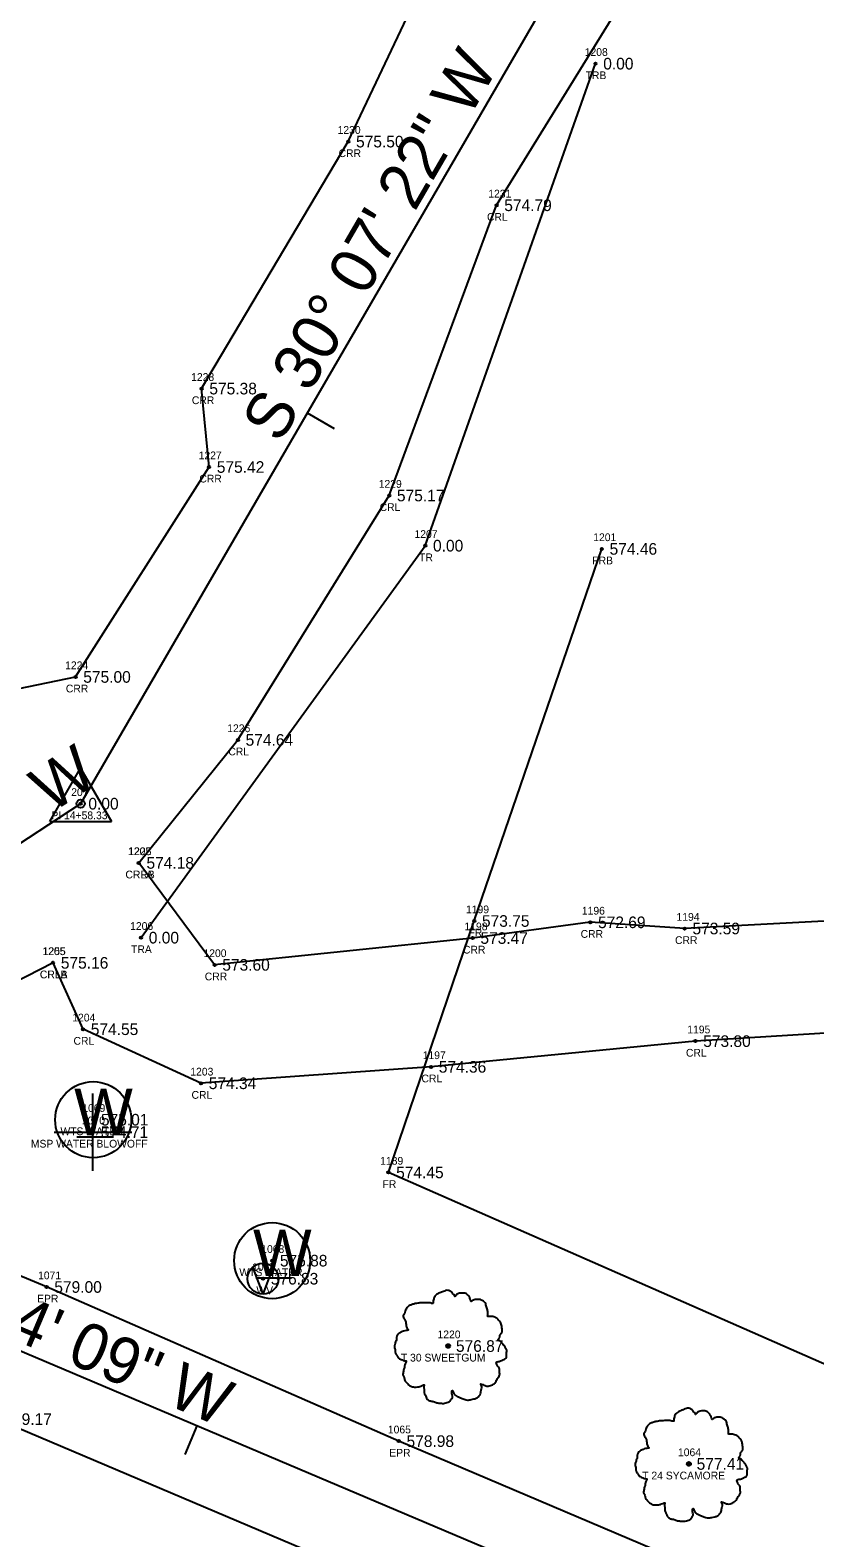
# Model space of a CAD drawing. Extents: x 1664393 to 1667175, y 987029 to 988607.
# Drawn here: x 1665562.7 to 1665664.1, y 987718.5 to 987913.2 of the extents above; entities that cross this region are included whole.
import ezdxf

# ---------------------------------------------------------------- set-up
doc = ezdxf.new("R2010")
doc.units = 0
for name, color, linetype in [('RD_EX_Fence_Other', 7, 'Continuous'), ('RD_EX_Fence_Other_txCode', 7, 'Continuous'), ('RD_EX_H2O', 7, 'Continuous'), ('RD_EX_H2O_txCode', 7, 'Continuous'), ('RD_EX_Misc', 7, 'Continuous'), ('RD_EX_Misc_txCode', 7, 'Continuous'), ('RD_EX_Road', 7, 'Continuous'), ('RD_EX_Road_txCode', 7, 'Continuous'), ('RD_EX_TX_Fence_Other_ELEV', 7, 'Continuous'), ('RD_EX_TX_H2O_ELEV', 7, 'Continuous'), ('RD_EX_TX_Misc_ELEV', 7, 'Continuous'), ('RD_EX_TX_Road_ELEV', 7, 'Continuous'), ('RD_EX_TX_UT_ELEV', 7, 'Continuous'), ('RD_EX_TX_VEG_ELEV', 7, 'Continuous'), ('RD_EX_UT', 7, 'Continuous'), ('RD_EX_UT_txCode', 7, 'Continuous'), ('RD_EX_VEG', 7, 'Continuous'), ('RD_EX_VEG_txCode', 7, 'Continuous'), ('RD_HC_Cl', 7, 'Continuous'), ('RD_HC_Data', 7, 'Continuous'), ('RD_HC_Data_Tic', 7, 'Continuous'), ('RD_HC_Survey_ELEV', 7, 'Continuous'), ('RD_HC_txCode', 7, 'Continuous'), ('RD_SMD_Locator', 7, 'Continuous')]:
    doc.layers.add(name, color=color, linetype=linetype)

msp = doc.modelspace()

# ---------------------------------------------------------------- linework, layer by layer
at = {"layer": 'RD_EX_Fence_Other'}
msp.add_lwpolyline([(1666177.67, 987530.31), (1666129.01, 987549.76), (1665988.61, 987609.56), (1665898.39, 987650), (1665744.33, 987706.22), (1665608.99, 987765.72), (1665620.07, 987798.18), (1665636.55, 987846.22)], dxfattribs=at)
at = {"layer": 'RD_EX_H2O'}
for points in [[(1665526.5, 987797.57), (1665535.59, 987808.2), (1665547.98, 987825.42), (1665568.59, 987829.69), (1665585.83, 987856.79), (1665584.87, 987866.91), (1665603.81, 987898.8), (1665618.99, 987930.85), (1665645.33, 987961.5), (1665639.67, 987994.37), (1665644.94, 988008.07), (1665639.5, 988048.94), (1665653.76, 988079.25), (1665684.31, 988124.82), (1665706.22, 988174.88), (1665711.8, 988227.54)], [(1665576.75, 987805.68), (1665589.55, 987821.56), (1665609.09, 987853.11), (1665622.95, 987890.58), (1665641.35, 987920.45), (1665654.29, 987935.19), (1665658.75, 987952.97), (1665657.67, 987971.74), (1665650.8, 987993.69), (1665662.98, 988008.61), (1665660.68, 988035.04), (1665652.89, 988045.21), (1665674.32, 988062.08), (1665698.86, 988119.64), (1665728.36, 988166.73), (1665725.83, 988226.06)], [(1665735.12, 987792.87), (1665681.63, 987799.03), (1665647.25, 987797.21), (1665635.06, 987798.01), (1665619.87, 987795.98), (1665586.54, 987792.52), (1665576.75, 987805.68)], [(1665565.69, 987792.78), (1665555.48, 987787.59), (1665542.58, 987772.17), (1665532.86, 987767.81), (1665532.86, 987767.81), (1665523.69, 987745.83), (1665522.12, 987740.87), (1665518.2, 987735.79), (1665482.82, 987708), (1665483.87, 987700.87), (1665513.49, 987706.09), (1665528.04, 987685.52), (1665561.97, 987665.98), (1665593.48, 987679.22), (1665619.37, 987685.12), (1665642.78, 987680.31), (1665663.97, 987651.85), (1665686.03, 987634.26), (1665705.62, 987627.98), (1665724.83, 987594.97)], [(1665733.23, 987780.02), (1665683.57, 987784.8), (1665648.64, 987782.67), (1665614.49, 987779.35), (1665584.79, 987777.23), (1665569.56, 987784.21), (1665565.69, 987792.78)]]:
    msp.add_lwpolyline(points, dxfattribs=at)
at = {"layer": 'RD_EX_Misc'}
for p, q in [((1665570.84, 987765.93), (1665570.84, 987775.93)), ((1665565.84, 987770.93), (1665575.84, 987770.93))]:
    msp.add_line(p, q, dxfattribs=at)
at = {"layer": 'RD_EX_Road'}
for points in [[(1666163.18, 987497.62), (1666116.6, 987517.39), (1666070.7, 987536.94), (1666024.42, 987556.43), (1665979.02, 987575.67), (1665932.35, 987595.55), (1665886.93, 987614.54), (1665839.87, 987634.25), (1665794.5, 987653.27), (1665748.81, 987672.51), (1665702.36, 987691.87), (1665656.42, 987711.45), (1665610.33, 987731.03), (1665564.85, 987750.93), (1665531.47, 987764.82)], [(1666156.67, 987480.61), (1666109.28, 987500.74), (1666063.55, 987520.04), (1666017.04, 987539.82), (1665971.11, 987559.14), (1665924.88, 987578.79), (1665879.5, 987597.89), (1665833.22, 987617.38), (1665786.91, 987636.81), (1665741.44, 987656.13), (1665695.81, 987675.2), (1665649.26, 987694.85), (1665603.56, 987714.71), (1665558.4, 987733.87), (1665524.71, 987748.93)]]:
    msp.add_lwpolyline(points, dxfattribs=at)
at = {"layer": 'RD_EX_UT'}
for p, q in [((1665568.75, 987770.32), (1665573.38, 987770.32)), ((1665592.8, 987750.01), (1665591.49, 987753.49)), ((1665592.8, 987750.01), (1665594.12, 987753.45)), ((1665591.85, 987752.12), (1665596.48, 987752.12))]:
    msp.add_line(p, q, dxfattribs=at)
for centre, radius in [((1665570.87, 987772.53), 4.91), ((1665593.98, 987754.33), 4.91), ((1665592.8, 987752), 2)]:
    msp.add_circle(centre, radius, dxfattribs=at)
at = {"layer": 'RD_EX_VEG'}
msp.add_lwpolyline([(1665577.05, 987796.03), (1665613.75, 987846.63), (1665635.73, 987908.86)], dxfattribs=at)
for centre, radius in [((1665616.71, 987743.31), 0.25), ((1665616.7, 987743.29), 0.0001), ((1665647.79, 987728.09), 0.25), ((1665647.78, 987728.08), 0.0001)]:
    msp.add_circle(centre, radius, dxfattribs=at)
for points in [[(1665616.85, 987750.48), (1665616.55, 987750.5), (1665616.22, 987750.4), (1665615.97, 987750.3), (1665615.75, 987750.23), (1665615.52, 987750.13), (1665615.22, 987749.95), (1665615, 987749.75), (1665614.87, 987749.5), (1665614.82, 987749.28), (1665614.77, 987749), (1665614.77, 987748.83), (1665614.65, 987748.8), (1665614.5, 987748.83), (1665614.25, 987748.9), (1665614, 987748.9), (1665613.75, 987748.9), (1665613.4, 987748.88), (1665613.05, 987748.88), (1665612.77, 987748.83), (1665612.45, 987748.78), (1665612.07, 987748.66), (1665611.72, 987748.53), (1665611.42, 987748.28), (1665611.17, 987747.81), (1665611.05, 987747.46), (1665610.9, 987747.21), (1665611.05, 987746.76), (1665611.22, 987746.41), (1665611.25, 987746.21), (1665611.32, 987745.78), (1665611.42, 987745.56), (1665611.55, 987745.36), (1665611.47, 987745.33), (1665611.1, 987745.28), (1665610.8, 987745.18), (1665610.37, 987744.96), (1665610.15, 987744.73), (1665610.05, 987744.41), (1665610.02, 987744.06), (1665609.92, 987743.86), (1665609.85, 987743.58), (1665609.82, 987743.51), (1665609.77, 987743.18), (1665609.87, 987742.73), (1665609.9, 987742.38), (1665610.02, 987742.16), (1665610.17, 987741.98), (1665610.35, 987741.73), (1665610.75, 987741.51), (1665611.07, 987741.41), (1665611.27, 987741.38), (1665611.1, 987740.88), (1665611.05, 987740.53), (1665610.92, 987740.13), (1665610.92, 987740.06), (1665610.87, 987739.58), (1665611.02, 987739.26), (1665611.1, 987738.88), (1665611.27, 987738.66), (1665611.55, 987738.36), (1665611.87, 987738.13), (1665612.37, 987738.01), (1665612.77, 987738.03), (1665613.35, 987738.21), (1665613.6, 987738.28), (1665613.57, 987738.11), (1665613.6, 987737.73), (1665613.6, 987737.31), (1665613.75, 987736.99), (1665613.85, 987736.71), (1665614, 987736.46), (1665614.32, 987736.24), (1665614.72, 987736.16), (1665615.15, 987736.01), (1665615.6, 987735.94), (1665616.1, 987735.91), (1665616.7, 987736.06), (1665616.97, 987736.19), (1665617.07, 987736.36), (1665617.27, 987736.74), (1665617.22, 987736.96), (1665617.25, 987737.56), (1665617.35, 987737.38), (1665617.52, 987737.04), (1665618.02, 987736.74), (1665618.42, 987736.56), (1665618.89, 987736.41), (1665619.19, 987736.34), (1665619.67, 987736.41), (1665620.04, 987736.49), (1665620.42, 987736.61), (1665620.72, 987736.89), (1665620.89, 987737.16), (1665620.94, 987737.43), (1665621.02, 987737.81), (1665621.07, 987737.98)], [(1665621.07, 987737.98), (1665620.99, 987738.16), (1665620.94, 987738.41), (1665621.02, 987738.38), (1665621.19, 987738.33), (1665621.47, 987738.21), (1665621.69, 987738.13), (1665622.02, 987738.16), (1665622.29, 987738.26), (1665622.74, 987738.53), (1665623.02, 987739.01), (1665623.29, 987739.41), (1665623.37, 987739.73), (1665623.32, 987739.96), (1665623.29, 987740.46), (1665623.09, 987740.71), (1665623.04, 987740.83), (1665622.94, 987741.23), (1665623.02, 987741.28), (1665623.29, 987741.33), (1665623.67, 987741.46), (1665623.94, 987741.58), (1665624.17, 987741.76), (1665624.24, 987741.98), (1665624.22, 987742.38), (1665624.27, 987742.78), (1665624.19, 987742.93), (1665624.09, 987743.08), (1665624.02, 987743.28), (1665623.87, 987743.43), (1665623.77, 987743.58), (1665623.67, 987743.68), (1665623.54, 987743.83), (1665623.37, 987743.96), (1665623.22, 987744.01), (1665623.17, 987744.16), (1665623.32, 987744.36), (1665623.37, 987744.46), (1665623.39, 987744.68), (1665623.62, 987745.03), (1665623.67, 987745.43), (1665623.62, 987745.86), (1665623.57, 987746.13), (1665623.42, 987746.41), (1665623.22, 987746.66), (1665623.09, 987746.83), (1665622.92, 987746.96), (1665622.59, 987747.08), (1665622.34, 987747.13), (1665621.99, 987747.13), (1665621.79, 987747.18), (1665621.82, 987747.23), (1665621.82, 987747.38), (1665621.82, 987747.66), (1665621.74, 987748.11), (1665621.59, 987748.61), (1665621.59, 987748.63), (1665621.49, 987748.88), (1665621.27, 987749.08), (1665621.09, 987749.18), (1665620.89, 987749.3), (1665620.64, 987749.33), (1665620.34, 987749.33), (1665620.07, 987749.28), (1665619.87, 987749.18), (1665619.69, 987749.05), (1665619.62, 987749.2), (1665619.52, 987749.5), (1665619.47, 987749.65), (1665619.32, 987749.83), (1665619.09, 987750.03), (1665618.64, 987750.15), (1665618.02, 987750.08), (1665617.72, 987749.88), (1665617.57, 987749.7), (1665617.52, 987749.83), (1665617.32, 987750.03), (1665617.22, 987750.2), (1665617.05, 987750.33), (1665616.9, 987750.43), (1665616.8, 987750.48)], [(1665647.93, 987735.26), (1665647.63, 987735.29), (1665647.3, 987735.19), (1665647.05, 987735.09), (1665646.83, 987735.01), (1665646.6, 987734.91), (1665646.3, 987734.74), (1665646.08, 987734.54), (1665645.95, 987734.29), (1665645.9, 987734.06), (1665645.85, 987733.79), (1665645.85, 987733.61), (1665645.73, 987733.59), (1665645.58, 987733.61), (1665645.33, 987733.69), (1665645.08, 987733.69), (1665644.83, 987733.69), (1665644.48, 987733.66), (1665644.13, 987733.66), (1665643.85, 987733.61), (1665643.53, 987733.56), (1665643.15, 987733.44), (1665642.8, 987733.31), (1665642.5, 987733.06), (1665642.25, 987732.59), (1665642.13, 987732.24), (1665641.98, 987731.99), (1665642.13, 987731.54), (1665642.3, 987731.19), (1665642.33, 987730.99), (1665642.4, 987730.56), (1665642.5, 987730.34), (1665642.63, 987730.14), (1665642.55, 987730.11), (1665642.18, 987730.06), (1665641.88, 987729.96), (1665641.45, 987729.74), (1665641.23, 987729.51), (1665641.13, 987729.19), (1665641.1, 987728.84), (1665641, 987728.64), (1665640.93, 987728.37), (1665640.9, 987728.29), (1665640.85, 987727.97), (1665640.95, 987727.52), (1665640.98, 987727.17), (1665641.1, 987726.94), (1665641.25, 987726.77), (1665641.43, 987726.52), (1665641.83, 987726.29), (1665642.15, 987726.19), (1665642.35, 987726.17), (1665642.18, 987725.67), (1665642.13, 987725.32), (1665642, 987724.92), (1665642, 987724.84), (1665641.95, 987724.37), (1665642.1, 987724.04), (1665642.18, 987723.67), (1665642.35, 987723.44), (1665642.63, 987723.14), (1665642.95, 987722.92), (1665643.45, 987722.79), (1665643.85, 987722.82), (1665644.43, 987722.99), (1665644.68, 987723.07), (1665644.65, 987722.89), (1665644.68, 987722.52), (1665644.68, 987722.09), (1665644.83, 987721.77), (1665644.93, 987721.49), (1665645.08, 987721.24), (1665645.4, 987721.02), (1665645.8, 987720.94), (1665646.23, 987720.79), (1665646.68, 987720.72), (1665647.18, 987720.69), (1665647.78, 987720.84), (1665648.05, 987720.97), (1665648.15, 987721.14), (1665648.35, 987721.52), (1665648.3, 987721.74), (1665648.33, 987722.34), (1665648.43, 987722.17), (1665648.6, 987721.82), (1665649.1, 987721.52), (1665649.5, 987721.34), (1665649.98, 987721.19), (1665650.28, 987721.12), (1665650.75, 987721.19), (1665651.12, 987721.27), (1665651.5, 987721.39), (1665651.8, 987721.67), (1665651.97, 987721.94), (1665652.02, 987722.22), (1665652.1, 987722.59), (1665652.15, 987722.77)], [(1665652.15, 987722.77), (1665652.07, 987722.94), (1665652.02, 987723.19), (1665652.1, 987723.17), (1665652.27, 987723.12), (1665652.55, 987722.99), (1665652.77, 987722.92), (1665653.1, 987722.94), (1665653.37, 987723.04), (1665653.82, 987723.32), (1665654.1, 987723.79), (1665654.37, 987724.19), (1665654.45, 987724.52), (1665654.4, 987724.74), (1665654.37, 987725.24), (1665654.17, 987725.49), (1665654.12, 987725.62), (1665654.02, 987726.02), (1665654.1, 987726.07), (1665654.37, 987726.12), (1665654.75, 987726.24), (1665655.02, 987726.37), (1665655.25, 987726.54), (1665655.32, 987726.77), (1665655.3, 987727.17), (1665655.35, 987727.57), (1665655.27, 987727.72), (1665655.17, 987727.87), (1665655.1, 987728.07), (1665654.95, 987728.22), (1665654.85, 987728.37), (1665654.75, 987728.46), (1665654.62, 987728.61), (1665654.45, 987728.74), (1665654.3, 987728.79), (1665654.25, 987728.94), (1665654.4, 987729.14), (1665654.45, 987729.24), (1665654.47, 987729.46), (1665654.7, 987729.81), (1665654.75, 987730.21), (1665654.7, 987730.64), (1665654.65, 987730.91), (1665654.5, 987731.19), (1665654.3, 987731.44), (1665654.17, 987731.61), (1665654, 987731.74), (1665653.67, 987731.86), (1665653.42, 987731.91), (1665653.07, 987731.91), (1665652.87, 987731.96), (1665652.9, 987732.01), (1665652.9, 987732.16), (1665652.9, 987732.44), (1665652.82, 987732.89), (1665652.67, 987733.39), (1665652.67, 987733.41), (1665652.57, 987733.66), (1665652.35, 987733.86), (1665652.17, 987733.96), (1665651.97, 987734.09), (1665651.72, 987734.11), (1665651.42, 987734.11), (1665651.15, 987734.06), (1665650.95, 987733.96), (1665650.78, 987733.84), (1665650.7, 987733.99), (1665650.6, 987734.29), (1665650.55, 987734.44), (1665650.4, 987734.61), (1665650.18, 987734.81), (1665649.73, 987734.94), (1665649.1, 987734.86), (1665648.8, 987734.66), (1665648.65, 987734.49), (1665648.6, 987734.61), (1665648.4, 987734.81), (1665648.3, 987734.99), (1665648.13, 987735.11), (1665647.98, 987735.21), (1665647.88, 987735.26)]]:
    msp.add_spline(points, degree=3, dxfattribs=at)
at = {"layer": 'RD_HC_Cl'}
for p, q in [((1666160.05, 987489.41), (1664963.07, 987995.8)), ((1665651.17, 987954.51), (1665569.25, 987813.32)), ((1665569.25, 987813.32), (1665529.15, 987787.05))]:
    msp.add_line(p, q, dxfattribs=at)
at = {"layer": 'RD_HC_Data'}
for p, q in [((1665565.28, 987811.02), (1665569.25, 987817.9)), ((1665569.25, 987817.9), (1665573.22, 987811.02)), ((1665565.28, 987811.02), (1665573.22, 987811.02))]:
    msp.add_line(p, q, dxfattribs=at)
msp.add_circle((1665569.25, 987813.32), 0.529, dxfattribs=at)
at = {"layer": 'RD_HC_Data_Tic'}
for p, q in [((1665598.52, 987863.77), (1665601.98, 987861.77)), ((1665584.25, 987733.01), (1665582.69, 987729.32))]:
    msp.add_line(p, q, dxfattribs=at)
at = {"layer": 'RD_SMD_Locator'}
for centre in [(1665635.73, 987908.86), (1665603.81, 987898.8), (1665622.95, 987890.58), (1665584.87, 987866.91), (1665585.83, 987856.79), (1665609.09, 987853.11), (1665613.75, 987846.63), (1665636.55, 987846.22), (1665568.59, 987829.69), (1665589.55, 987821.56), (1665569.25, 987813.32), (1665576.75, 987805.68), (1665576.75, 987805.68), (1665620.07, 987798.18), (1665635.06, 987798.01), (1665647.25, 987797.21), (1665577.05, 987796.03), (1665619.87, 987795.98), (1665565.69, 987792.78), (1665565.69, 987792.78), (1665586.54, 987792.52), (1665569.56, 987784.21), (1665648.64, 987782.67), (1665614.49, 987779.35), (1665584.79, 987777.23), (1665570.87, 987772.53), (1665570.84, 987770.93), (1665608.99, 987765.72), (1665593.98, 987754.33), (1665564.85, 987750.93), (1665592.8, 987752), (1665616.71, 987743.31), (1665610.33, 987731.03), (1665647.79, 987728.09)]:
    msp.add_circle(centre, 0.15, dxfattribs=at)

# ---------------------------------------------------------------- texts
at = {"layer": 'RD_EX_Fence_Other_txCode'}
for s, p in [('1201', (1665635.44, 987847.22)), ('FRB', (1665635.32, 987844.22)), ('1199', (1665619.01, 987799.18)), ('FR', (1665619.32, 987796.18)), ('1189', (1665607.93, 987766.72)), ('FR', (1665608.23, 987763.72))]:
    msp.add_text(s, height=1, dxfattribs=at).set_placement(p)
at = {"layer": 'RD_EX_H2O_txCode'}
for s, p in [('1230', (1665602.43, 987899.8)), ('CRR', (1665602.56, 987896.8)), ('1231', (1665621.89, 987891.58)), ('CRL', (1665621.72, 987888.58)), ('1228', (1665583.52, 987867.91)), ('CRR', (1665583.61, 987864.91)), ('1227', (1665584.49, 987857.79)), ('CRR', (1665584.58, 987854.79)), ('1229', (1665607.74, 987854.11)), ('CRL', (1665607.86, 987851.11)), ('1224', (1665567.25, 987830.69)), ('CRR', (1665567.34, 987827.69)), ('1226', (1665588.18, 987822.56)), ('CRL', (1665588.32, 987819.56)), ('1202', (1665575.37, 987806.68)), ('1225', (1665575.41, 987806.68)), ('CRRB', (1665575.03, 987803.68)), ('CRLA', (1665575.04, 987803.68)), ('1196', (1665633.97, 987799.01)), ('1194', (1665646.19, 987798.21)), ('1198', (1665618.81, 987796.98)), ('CRR', (1665633.81, 987796.01)), ('CRR', (1665646, 987795.21)), ('1205', (1665564.31, 987793.78)), ('1255', (1665564.35, 987793.78)), ('1200', (1665585.11, 987793.52)), ('CRR', (1665618.62, 987793.98)), ('CRLA', (1665563.98, 987790.78)), ('CRLB', (1665563.99, 987790.78)), ('CRR', (1665585.28, 987790.52)), ('1204', (1665568.17, 987785.21)), ('1195', (1665647.58, 987783.67)), ('CRL', (1665568.33, 987782.21)), ('CRL', (1665647.41, 987780.67)), ('1197', (1665613.42, 987780.35)), ('1203', (1665583.41, 987778.23)), ('CRL', (1665613.26, 987777.35)), ('CRL', (1665583.57, 987775.23))]:
    msp.add_text(s, height=1, dxfattribs=at).set_placement(p)
at = {"layer": 'RD_EX_Misc_txCode'}
for s, p in [('1070', (1665569.42, 987771.93)), ('MSP WATER BLOWOFF', (1665562.82, 987768.93))]:
    msp.add_text(s, height=1, dxfattribs=at).set_placement(p)
at = {"layer": 'RD_EX_Road_txCode'}
for s, p in [('1071', (1665563.75, 987751.93)), ('EPR', (1665563.63, 987748.93)), ('1065', (1665608.92, 987732.03)), ('EPR', (1665609.1, 987729.03))]:
    msp.add_text(s, height=1, dxfattribs=at).set_placement(p)
at = {"layer": 'RD_EX_TX_Fence_Other_ELEV'}
for s, p in [('574.46', (1665637.55, 987845.47)), ('573.75', (1665621.07, 987797.43)), ('574.45', (1665609.99, 987764.97))]:
    msp.add_text(s, height=1.5, dxfattribs=at).set_placement(p)
at = {"layer": 'RD_EX_TX_H2O_ELEV'}
for s, p in [('575.50', (1665604.81, 987898.05)), ('574.79', (1665623.95, 987889.83)), ('575.38', (1665585.87, 987866.16)), ('575.42', (1665586.83, 987856.04)), ('575.17', (1665610.09, 987852.36)), ('575.00', (1665569.59, 987828.94)), ('574.64', (1665590.55, 987820.81)), ('574.18', (1665577.75, 987804.93)), ('574.18', (1665577.75, 987804.93)), ('572.69', (1665636.06, 987797.26)), ('573.59', (1665648.25, 987796.46)), ('573.47', (1665620.87, 987795.23)), ('575.16', (1665566.69, 987792.03)), ('575.16', (1665566.69, 987792.03)), ('573.60', (1665587.54, 987791.77)), ('574.55', (1665570.56, 987783.46)), ('573.80', (1665649.64, 987781.92)), ('574.36', (1665615.49, 987778.6)), ('574.34', (1665585.79, 987776.48))]:
    msp.add_text(s, height=1.5, dxfattribs=at).set_placement(p)
at = {"layer": 'RD_EX_TX_Misc_ELEV'}
msp.add_text('574.71', height=1.5, dxfattribs=at).set_placement((1665571.84, 987770.18))
at = {"layer": 'RD_EX_TX_Road_ELEV'}
for s, p in [('579.00', (1665565.85, 987750.18)), ('579.17', (1665559.4, 987733.12)), ('578.98', (1665611.33, 987730.28))]:
    msp.add_text(s, height=1.5, dxfattribs=at).set_placement(p)
at = {"layer": 'RD_EX_TX_UT_ELEV'}
for s, p in [('575.01', (1665571.87, 987771.78)), ('575.88', (1665594.98, 987753.58)), ('576.83', (1665593.8, 987751.25))]:
    msp.add_text(s, height=1.5, dxfattribs=at).set_placement(p)
at = {"layer": 'RD_EX_TX_VEG_ELEV'}
for s, p in [('0.00', (1665636.73, 987908.11)), ('0.00', (1665614.75, 987845.88)), ('0.00', (1665578.05, 987795.28)), ('576.87', (1665617.71, 987742.56)), ('577.41', (1665648.79, 987727.34))]:
    msp.add_text(s, height=1.5, dxfattribs=at).set_placement(p)
at = {"layer": 'RD_EX_UT'}
for p in [(1665568.41, 987770.53), (1665591.51, 987752.33)]:
    msp.add_text('W', height=6, dxfattribs=at).set_placement(p)
at = {"layer": 'RD_EX_UT_txCode'}
for s, p in [('1069', (1665569.46, 987773.53)), ('WTS WATER', (1665566.64, 987770.53)), ('1068', (1665592.57, 987755.33)), ('WTS WATER', (1665589.74, 987752.33)), ('1067', (1665591.39, 987753)), ('WV', (1665591.94, 987750))]:
    msp.add_text(s, height=1, dxfattribs=at).set_placement(p)
at = {"layer": 'RD_EX_VEG_txCode'}
for s, p in [('1208', (1665634.34, 987909.86)), ('TRB', (1665634.46, 987906.86)), ('1207', (1665612.36, 987847.63)), ('TR', (1665612.95, 987844.63)), ('1206', (1665575.64, 987797.03)), ('TRA', (1665575.76, 987794.03)), ('1220', (1665615.33, 987744.31)), ('T 30 SWEETGUM', (1665610.6, 987741.31)), ('1064', (1665646.38, 987729.09)), ('T 24 SYCAMORE', (1665641.76, 987726.09))]:
    msp.add_text(s, height=1, dxfattribs=at).set_placement(p)
at = {"layer": 'RD_HC_Data'}
for s, rotation, p in [('S 30%%d 07\' 22" W', 59.8772, (1665595, 987859.69)), ('S 56%%d 46\' 31" W', 33.2247, (1665524.74, 987785.36)), ('N 67%%d 04\' 09" W', 337.0693, (1665534.95, 987754.95))]:
    msp.add_text(s, height=6, rotation=rotation, dxfattribs=at).set_placement(p)
at = {"layer": 'RD_HC_Survey_ELEV'}
msp.add_text('0.00', height=1.5, dxfattribs=at).set_placement((1665570.25, 987812.57))
at = {"layer": 'RD_HC_txCode'}
for s, p in [('207', (1665568.03, 987814.32)), ('PI 14+58.33', (1665565.47, 987811.32))]:
    msp.add_text(s, height=1, dxfattribs=at).set_placement(p)

doc.saveas('drawing.dxf')
